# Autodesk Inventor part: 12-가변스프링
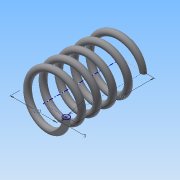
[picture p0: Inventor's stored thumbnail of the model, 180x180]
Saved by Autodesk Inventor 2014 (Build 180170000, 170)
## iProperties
Created: 2015-09
Part Number: 12-가변스프링
Material: 강철, 탄소
Document SubType Name: Modeling
Designer: study
Density: 7.87 g/cm^3
Appearance: 반연마
Mass: 18.8817 g
Surface Area: 32.5359 cm^2
Volume: 2.3992 cm^3
Author: study
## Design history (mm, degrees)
sketch "스케치1"
  geometry: L1 (0, 0)-(11, 0); L2 (11, 0)-(11, 36.261); L3 (11, 36.261)-(0, 36.261); L4 (0, 36.261)-(0, 0); C1 r 1.5 at (11, 0)
  constraints: 8 end point, 2 parallel, 1 centre point, 1 coincident, 1 horizontal, 1 perpendicular
  dimensions: "d0" = 3 diameter of C1; "d1" = 22 diameter of L1.end L4; "d2" = 36.2612 distance of L1.end L2.end (derived)
feature "코일1" sketch "스케치1" pitch "d3" = 10; turns "d5" = 5; dims "d4" = 36.2612 (= d2), "d6" = 0, angle "d7" = 90 deg, angle "d8" = 90 deg, "d9" = 0, "d10" = 0
node "작업 평면1"
sketch "스케치2"
  geometry: L1 (-12.5, 0)-(-9.5, 0) reference; 1 further point
  constraints: 1 horizontal alignment
extrude "돌출1" cut sketch "스케치2" stored distance "d12" = 10; taper "d13" = 0 deg
node "작업 평면2"
sketch "스케치3"
  geometry: L1 (-9.5, 0)-(-12.5, 0) reference; 1 further point
  constraints: 1 horizontal alignment
extrude "돌출2" cut sketch "스케치3" stored distance "d15" = 10; taper "d16" = 0 deg
node "솔리드1"
node "절단 모서리 투영1"
node "절단 모서리 투영2"
other parameters: "d11" = 0, "d14" = 36.2612 (= d2)
